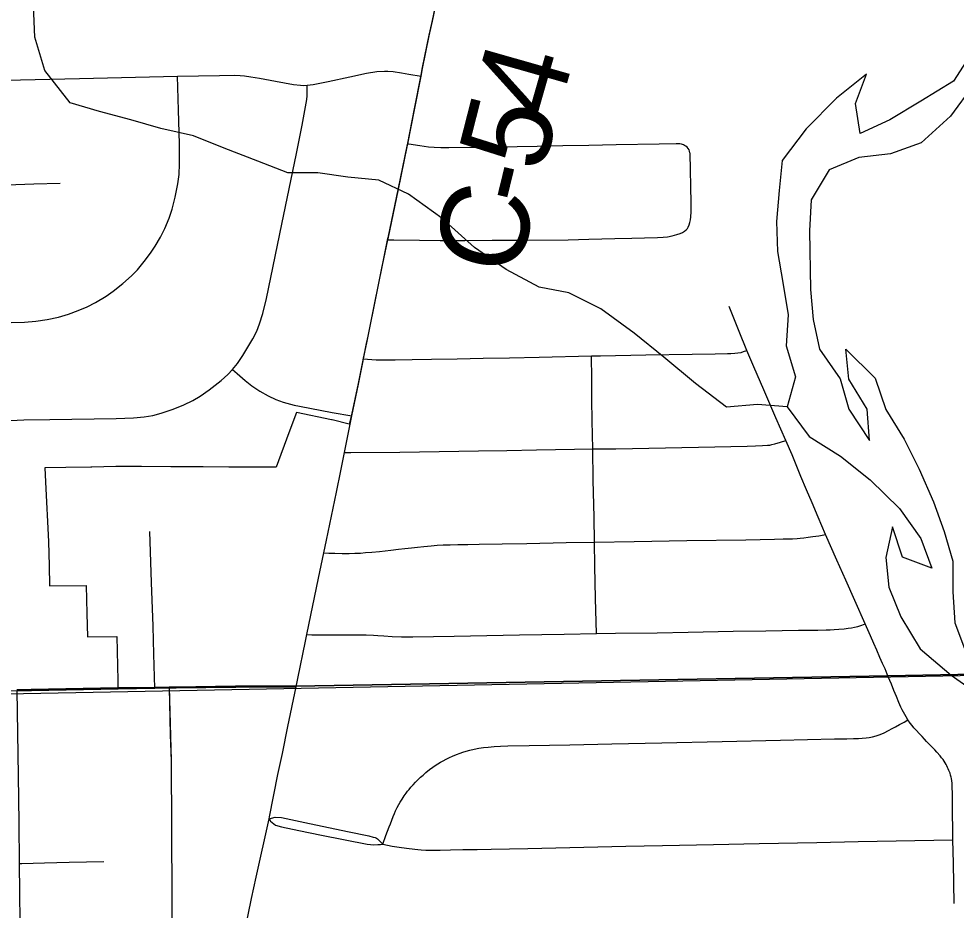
# Model space of a CAD drawing. Extents: x -6.4 to 34, y -4.2 to 22.
# Drawn here: x 4.056 to 4.662, y 15.706 to 16.282 of the extents above; entities that cross this region are included whole.
import ezdxf

# ---------------------------------------------------------------- set-up
doc = ezdxf.new("R2010")
doc.units = 0
for name, color, linetype in [('GM_X_City_Street', 7, 'Continuous'), ('GM_X_Corporation', 7, 'Continuous'), ('GM_X_County_Road', 7, 'Continuous'), ('GM_X_County_Road_Text', 7, 'Continuous'), ('GM_X_Major_River', 7, 'Continuous'), ('GM_X_Minor_River', 7, 'Continuous'), ('GM_X_Township_Road', 7, 'Continuous')]:
    doc.layers.add(name, color=color, linetype=linetype)

msp = doc.modelspace()

# ---------------------------------------------------------------- linework, layer by layer
at = {"layer": 'GM_X_City_Street'}
for points in [[(4.29434, 16.13894), (4.2983, 16.1389), (4.31489, 16.13876), (4.32819, 16.13864), (4.34402, 16.1386), (4.36176, 16.13867), (4.3816, 16.13883), (4.41095, 16.13907), (4.42419, 16.13937), (4.44106, 16.13976), (4.45211, 16.14005), (4.46018, 16.14027), (4.4686, 16.14049), (4.47232, 16.14072), (4.47512, 16.141), (4.47823, 16.14158), (4.48114, 16.14241), (4.48324, 16.1431), (4.48483, 16.14382), (4.48624, 16.1446), (4.48725, 16.14536), (4.48805, 16.1462), (4.48852, 16.14707), (4.48914, 16.14861), (4.48962, 16.1501), (4.49006, 16.15195), (4.49029, 16.15384), (4.4904, 16.15702), (4.49038, 16.1629), (4.48979, 16.19469), (4.48968, 16.19532), (4.48947, 16.19628), (4.48909, 16.19718), (4.48854, 16.19804), (4.48786, 16.19888), (4.48701, 16.19957), (4.48621, 16.20006), (4.48555, 16.20043), (4.48428, 16.2008), (4.48314, 16.20097), (4.48214, 16.201), (4.48069, 16.201), (4.46975, 16.20085), (4.44199, 16.20047), (4.42426, 16.20006), (4.4075, 16.19967), (4.39089, 16.19927), (4.35195, 16.19863), (4.3337, 16.19836), (4.3285, 16.19843), (4.32419, 16.19861), (4.32067, 16.19884), (4.31507, 16.19971), (4.308, 16.20087), (4.30722, 16.20099)], [(4.66044, 15.70999), (4.65997, 15.73598), (4.65956, 15.75111), (4.65941, 15.77505), (4.65942, 15.78015), (4.65926, 15.78598), (4.65918, 15.78763), (4.65902, 15.78911), (4.65877, 15.7906), (4.65852, 15.79166), (4.6582, 15.79289), (4.65779, 15.79405), (4.65746, 15.79495), (4.65705, 15.79594), (4.65664, 15.79693), (4.65623, 15.79783), (4.65573, 15.79882), (4.65524, 15.79972), (4.65467, 15.80079), (4.65401, 15.80186), (4.65327, 15.80294), (4.65236, 15.80417), (4.65146, 15.80532), (4.64937, 15.8077), (4.648, 15.80919), (4.64612, 15.81116), (4.64407, 15.81322), (4.64265, 15.81468), (4.64131, 15.81606), (4.63971, 15.81775), (4.63798, 15.81964), (4.63581, 15.82195), (4.63445, 15.82342), (4.63322, 15.82491), (4.63194, 15.82656), (4.63058, 15.82859), (4.62939, 15.83051), (4.62853, 15.83198), (4.62763, 15.83363), (4.6268, 15.83519), (4.62603, 15.83684), (4.62541, 15.83824), (4.62472, 15.83981), (4.62319, 15.84367), (4.62156, 15.84768), (4.61996, 15.85161), (4.61791, 15.85654), (4.61581, 15.86152), (4.61413, 15.86511), (4.61244, 15.869), (4.61047, 15.87361), (4.60858, 15.87797), (4.60644, 15.88291), (4.60291, 15.89064), (4.59634, 15.90586), (4.59048, 15.91892), (4.58468, 15.93186), (4.57729, 15.94847), (4.57253, 15.95974), (4.56866, 15.9689), (4.56508, 15.97739), (4.56144, 15.98599), (4.55578, 15.99989), (4.55175, 16.00919), (4.54527, 16.02383), (4.53738, 16.04193), (4.53098, 16.0569), (4.52646, 16.06743), (4.52146, 16.07977), (4.51508, 16.09592)], [(4.27864, 16.06202), (4.28115, 16.06179), (4.28395, 16.06154), (4.28683, 16.06138), (4.28995, 16.06129), (4.2939, 16.06133), (4.29907, 16.06137), (4.31001, 16.06156), (4.32266, 16.06179), (4.33921, 16.06212), (4.35591, 16.06239), (4.37294, 16.06271), (4.39224, 16.06317), (4.42596, 16.06387), (4.43182, 16.06399), (4.4611, 16.06454), (4.49104, 16.06502), (4.50592, 16.06525), (4.51399, 16.06541), (4.51613, 16.0655), (4.51875, 16.06566), (4.52056, 16.06582), (4.52279, 16.06623), (4.52433, 16.06669), (4.52646, 16.06743)], [(4.42921, 15.88438), (4.4286, 15.90718), (4.4282, 15.92799), (4.42788, 15.94344), (4.42765, 15.95974), (4.42717, 15.98351), (4.42681, 16.00377), (4.42637, 16.02192), (4.42626, 16.03573), (4.42615, 16.04897), (4.42596, 16.06387)], [(4.2664, 16.0015), (4.27044, 16.00151), (4.3022, 16.00159), (4.35293, 16.00252), (4.37135, 16.00284), (4.39052, 16.00323), (4.41494, 16.00363), (4.42681, 16.00377), (4.44175, 16.00394), (4.49522, 16.00497), (4.52663, 16.00549), (4.53214, 16.00569), (4.5365, 16.00593), (4.53971, 16.00618), (4.54123, 16.00632), (4.5425, 16.00659), (4.54456, 16.00708), (4.54818, 16.00814), (4.55175, 16.00919)], [(4.1437, 15.84907), (4.1431, 15.87118), (4.14254, 15.88911), (4.14149, 15.91732), (4.14053, 15.95047)], [(4.25298, 15.93658), (4.25618, 15.93649), (4.26004, 15.93637), (4.26481, 15.93624), (4.26942, 15.93623), (4.27311, 15.93631), (4.27657, 15.93649), (4.27986, 15.93672), (4.28397, 15.93705), (4.28891, 15.93754), (4.29269, 15.93794), (4.29631, 15.93835), (4.30124, 15.93892), (4.30536, 15.93941), (4.30955, 15.9399), (4.31358, 15.94031), (4.3177, 15.94072), (4.32246, 15.94113), (4.32617, 15.94146), (4.3302, 15.9417), (4.33455, 15.94186), (4.33957, 15.94202), (4.34607, 15.9421), (4.35339, 15.94226), (4.3682, 15.94245), (4.38431, 15.94265), (4.40973, 15.94321), (4.42788, 15.94344), (4.45356, 15.94392), (4.48761, 15.94455), (4.52578, 15.94502), (4.54428, 15.94542), (4.54995, 15.94556), (4.55382, 15.94566), (4.55604, 15.94576), (4.55901, 15.94589), (4.56088, 15.94607), (4.56327, 15.94631), (4.56599, 15.94664), (4.56911, 15.94711), (4.5729, 15.9477), (4.57729, 15.94847)], [(4.24204, 15.8837), (4.24514, 15.88368), (4.25657, 15.88359), (4.27442, 15.88358), (4.28042, 15.88349), (4.28511, 15.88332), (4.28798, 15.88317), (4.29177, 15.88291), (4.29712, 15.88257), (4.3032, 15.8824), (4.3106, 15.8824), (4.33717, 15.88279), (4.37936, 15.88358), (4.40831, 15.88397), (4.42921, 15.88438), (4.44154, 15.88461), (4.46843, 15.88496), (4.48842, 15.88524), (4.51753, 15.88588), (4.53875, 15.88616), (4.55989, 15.8865), (4.5723, 15.88666), (4.57765, 15.88681), (4.5802, 15.8869), (4.58299, 15.8871), (4.58587, 15.88731), (4.58925, 15.88755), (4.59204, 15.8878), (4.5941, 15.88804), (4.59608, 15.88845), (4.59813, 15.88903), (4.60069, 15.88982), (4.60291, 15.89064)], [(4.2911, 15.74817), (4.29313, 15.75376), (4.2942, 15.75672), (4.29519, 15.75935), (4.29602, 15.7614), (4.29692, 15.76371), (4.29783, 15.76609), (4.29857, 15.76798), (4.29939, 15.76987), (4.3003, 15.77185), (4.30137, 15.77382), (4.30227, 15.7753), (4.30355, 15.77725), (4.30491, 15.77941), (4.30615, 15.78114), (4.30715, 15.78246), (4.30812, 15.78369), (4.30927, 15.785), (4.31069, 15.78657), (4.31224, 15.78828), (4.31396, 15.79001), (4.31553, 15.79149), (4.31709, 15.79289), (4.319, 15.79454), (4.32129, 15.79642), (4.32335, 15.79798), (4.32491, 15.79905), (4.32656, 15.80012), (4.32845, 15.80127), (4.33009, 15.80217), (4.33207, 15.80324), (4.33413, 15.80423), (4.3361, 15.80513), (4.33865, 15.8062), (4.34104, 15.8071), (4.34292, 15.80776), (4.34498, 15.80842), (4.34745, 15.80907), (4.35016, 15.80973), (4.35321, 15.8103), (4.35625, 15.81071), (4.3593, 15.81104), (4.36308, 15.81136), (4.36711, 15.8116), (4.37188, 15.81177), (4.38561, 15.81201), (4.4121, 15.81248), (4.43916, 15.81304), (4.47148, 15.81367), (4.51038, 15.81464), (4.54821, 15.81559), (4.58316, 15.81631), (4.59114, 15.81639), (4.59542, 15.81647), (4.59854, 15.81655), (4.60093, 15.81671), (4.6035, 15.81697), (4.60545, 15.81725), (4.60759, 15.81769), (4.61006, 15.81835), (4.61253, 15.81917), (4.61516, 15.82032), (4.61796, 15.82163), (4.62043, 15.82295), (4.62257, 15.8241), (4.6252, 15.82558), (4.62816, 15.82722), (4.63058, 15.82859)], [(4.21758, 15.76472), (4.2214, 15.76569), (4.22554, 15.76549), (4.24063, 15.76224), (4.26832, 15.75641), (4.28213, 15.75353), (4.28476, 15.75287), (4.28616, 15.75246), (4.28698, 15.75205), (4.28756, 15.75163), (4.28854, 15.75073), (4.28961, 15.74966), (4.2911, 15.74817)], [(4.21758, 15.76472), (4.21856, 15.76313), (4.22176, 15.76057), (4.22569, 15.75935), (4.23674, 15.75709), (4.25155, 15.75412), (4.28099, 15.74826), (4.28312, 15.74793), (4.28526, 15.74785), (4.28781, 15.74801), (4.28954, 15.74809), (4.2911, 15.74817)], [(4.2911, 15.74817), (4.29718, 15.74701), (4.30318, 15.74601), (4.3082, 15.74535), (4.31363, 15.74478), (4.31584, 15.74464), (4.31897, 15.74444), (4.32275, 15.74436), (4.3281, 15.74439), (4.33485, 15.74451), (4.34274, 15.74469), (4.35203, 15.74488), (4.36124, 15.74507), (4.38493, 15.74555), (4.44826, 15.7469), (4.47195, 15.74746), (4.50484, 15.7481), (4.53437, 15.74865), (4.57171, 15.74937), (4.59836, 15.74993), (4.65956, 15.75111)]]:
    msp.add_lwpolyline(points, dxfattribs=at)
at = {"layer": 'GM_X_Corporation'}
for points in [[(4.32878, 16.30877), (4.32292, 16.28089), (4.32092, 16.27139), (4.31657, 16.25039), (4.3156, 16.24542), (4.31133, 16.2236), (4.30702, 16.20155), (4.30664, 16.19956), (4.30094, 16.17237), (4.29431, 16.14028), (4.29422, 16.13988), (4.28045, 16.07241), (4.27844, 16.06257), (4.27795, 16.06015), (4.27515, 16.04617), (4.2709, 16.02585), (4.26942, 16.01979), (4.25827, 16.02251), (4.25817, 16.02254), (4.25808, 16.02257), (4.25798, 16.02259), (4.25789, 16.02261), (4.23524, 16.02735), (4.23036, 16.01424), (4.22206, 15.99193), (4.20424, 15.99202), (4.19724, 15.99206), (4.19162, 15.99209), (4.17488, 15.99218), (4.15558, 15.99228), (4.15407, 15.99229), (4.13512, 15.99239), (4.1186, 15.99247), (4.10294, 15.99208), (4.10223, 15.99206), (4.08613, 15.99173), (4.07253, 15.99157), (4.07323, 15.97799), (4.07474, 15.94832), (4.07487, 15.94366), (4.07529, 15.9285), (4.07565, 15.91517), (4.09924, 15.91546), (4.09973, 15.89748), (4.10015, 15.88232), (4.11909, 15.88253), (4.11987, 15.85408), (4.1197, 15.84929), (4.1435, 15.84962), (4.15304, 15.84978), (4.1542, 15.80243), (4.15484, 15.66937)], [(5.03555, 15.86533), (4.94435, 15.86353), (4.89919, 15.86252), (4.61771, 15.8571), (4.23487, 15.85045), (4.22882, 15.85045), (4.19578, 15.85041), (4.15725, 15.84984), (4.15304, 15.84978), (4.1435, 15.84962), (4.1197, 15.84929), (4.06372, 15.84822), (4.05453, 15.84804)], [(4.05453, 15.84804), (4.06372, 15.84822), (4.1197, 15.84929), (4.1435, 15.84962), (4.15304, 15.84978), (4.15725, 15.84984), (4.19578, 15.85041), (4.22882, 15.85045), (4.23487, 15.85045), (4.61771, 15.8571), (4.89919, 15.86252), (4.94435, 15.86353), (5.03555, 15.86533)]]:
    msp.add_lwpolyline(points, dxfattribs=at)
msp.add_lwpolyline([(3.94651, 15.8436), (4.81021, 15.86007), (4.82849, 15.2133), (4.41851, 15.20239), (4.0324, 15.19212), (3.70187, 15.18694), (3.30855, 15.18118), (3.23887, 15.18016), (3.22314, 15.8313)], close=True, dxfattribs=at)
at = {"layer": 'GM_X_County_Road'}
for p, q in [((4.1437, 15.84907), (4.15324, 15.84922)), ((4.1199, 15.84874), (4.1437, 15.84907))]:
    msp.add_line(p, q, dxfattribs=at)
for points in [[(4.27109, 16.02529), (4.27534, 16.04561), (4.27815, 16.05959), (4.27864, 16.06202), (4.28065, 16.07185), (4.28165, 16.07677), (4.28579, 16.09714), (4.29095, 16.12254), (4.29434, 16.13894), (4.29451, 16.13972), (4.30114, 16.17182), (4.30684, 16.19901), (4.30722, 16.20099), (4.31153, 16.22305), (4.3158, 16.24487), (4.31677, 16.24984), (4.32112, 16.27084), (4.32312, 16.28033), (4.32897, 16.30822), (4.33191, 16.32276), (4.33391, 16.33314), (4.34092, 16.36958), (4.3432, 16.38194)], [(4.23507, 15.8499), (4.23619, 15.85529), (4.24118, 15.87956), (4.24204, 15.8837), (4.24962, 15.92029), (4.25298, 15.93658), (4.25466, 15.94473), (4.26106, 15.97577), (4.26395, 15.98957), (4.2664, 16.0015), (4.26705, 16.00464), (4.27109, 16.02529)], [(4.15324, 15.84922), (4.15745, 15.84928), (4.19598, 15.84986), (4.22901, 15.84989), (4.23507, 15.8499)], [(4.19951, 15.68041), (4.20622, 15.71312), (4.20924, 15.72684), (4.21758, 15.76472), (4.21784, 15.76592), (4.22333, 15.79328), (4.22617, 15.80685), (4.22977, 15.82429), (4.23507, 15.8499)], [(3.51043, 15.83841), (3.55892, 15.83944), (3.60948, 15.8405), (3.64235, 15.8411), (3.67734, 15.84142), (3.68745, 15.84152), (3.70213, 15.84176), (3.77183, 15.8429), (3.79297, 15.84325), (3.85029, 15.84411), (3.9112, 15.84501), (3.92879, 15.84528), (3.97764, 15.84601), (4.05473, 15.84749), (4.06392, 15.84766), (4.1199, 15.84874)]]:
    msp.add_lwpolyline(points, dxfattribs=at)
at = {"layer": 'GM_X_Major_River'}
for points in [[(4.67245, 16.2609), (4.65997, 16.24165), (4.63902, 16.22868), (4.61882, 16.21648), (4.59968, 16.20772), (4.59663, 16.22702), (4.60381, 16.24615), (4.58443, 16.23055), (4.56476, 16.21077), (4.54928, 16.19032), (4.54741, 16.17092), (4.54556, 16.15077), (4.54634, 16.13142), (4.54979, 16.11138), (4.55325, 16.09058), (4.55178, 16.07042), (4.55788, 16.05044), (4.55261, 16.03096), (4.56664, 16.0119), (4.58699, 15.99905), (4.60625, 15.9839), (4.6252, 15.96533), (4.63886, 15.94588), (4.64608, 15.92667), (4.62699, 15.93386), (4.62052, 15.95346), (4.61639, 15.93363), (4.61831, 15.91431), (4.62591, 15.89512), (4.63846, 15.87451), (4.65852, 15.85748), (4.67966, 15.84274)], [(4.6729, 16.23927), (4.65817, 16.21884), (4.63921, 16.20173), (4.61928, 16.19448), (4.59887, 16.19214), (4.57972, 16.18414), (4.568, 16.16491), (4.5669, 16.14477), (4.56769, 16.10683), (4.56923, 16.0875), (4.57342, 16.06823), (4.5867, 16.04915), (4.59241, 16.02954), (4.60572, 16.00932), (4.60416, 16.02941), (4.59239, 16.0489), (4.59047, 16.06821), (4.60942, 16.04964), (4.61629, 16.02929), (4.62805, 16.01018), (4.63793, 15.99065), (4.64708, 15.96959), (4.65392, 15.95037), (4.65963, 15.93114), (4.65966, 15.9114), (4.66084, 15.89131), (4.66846, 15.87135)]]:
    msp.add_lwpolyline(points, dxfattribs=at)
at = {"layer": 'GM_X_Minor_River'}
msp.add_lwpolyline([(4.55261, 16.03096), (4.53325, 16.03245), (4.51321, 16.03088), (4.49319, 16.04602), (4.47276, 16.06304), (4.45349, 16.07858), (4.43195, 16.09444), (4.41128, 16.10463), (4.39225, 16.1084), (4.37081, 16.11971), (4.35043, 16.13408), (4.3292, 16.15298), (4.30766, 16.16846), (4.28853, 16.17755), (4.26841, 16.17939), (4.24903, 16.1824), (4.22971, 16.18237), (4.21023, 16.18992), (4.18846, 16.19819), (4.1686, 16.20611), (4.14766, 16.21098), (4.12822, 16.21664), (4.10803, 16.2219), (4.08897, 16.22757), (4.07263, 16.24848), (4.06612, 16.26998), (4.06531, 16.29046)], dxfattribs=at)
at = {"layer": 'GM_X_Township_Road'}
for points in [[(4.03743, 16.24208), (4.09493, 16.24339), (4.1584, 16.24469), (4.18562, 16.24531), (4.19552, 16.24541), (4.19894, 16.24521), (4.20164, 16.245), (4.20586, 16.24445), (4.21141, 16.24357), (4.22175, 16.24157), (4.2334, 16.23931), (4.23783, 16.23888), (4.23986, 16.23878), (4.24215, 16.23897), (4.24605, 16.2394), (4.25582, 16.24128), (4.26975, 16.24442), (4.28064, 16.24674), (4.28733, 16.24774), (4.29218, 16.24809), (4.29432, 16.24809), (4.29769, 16.24782), (4.30315, 16.247), (4.308, 16.24618), (4.3158, 16.24487)], [(4.05075, 16.08562), (4.05941, 16.08575), (4.06678, 16.08641), (4.07411, 16.0875), (4.08135, 16.08903), (4.08786, 16.09093), (4.09424, 16.0932), (4.09987, 16.09566), (4.10534, 16.09849), (4.11225, 16.10257), (4.11678, 16.10575), (4.12305, 16.11077), (4.12857, 16.1157), (4.13242, 16.11968), (4.13678, 16.12486), (4.14085, 16.1303), (4.14393, 16.13491), (4.14735, 16.14074), (4.15012, 16.14626), (4.15301, 16.15307), (4.15502, 16.15888), (4.15695, 16.16666), (4.1586, 16.17515), (4.15935, 16.18126), (4.15969, 16.18803), (4.15968, 16.20105), (4.15896, 16.22281), (4.1584, 16.24469)], [(4.0504, 16.02219), (4.05903, 16.02266), (4.07577, 16.02289), (4.11868, 16.02344), (4.12992, 16.02383), (4.13679, 16.0245), (4.14238, 16.02546), (4.14786, 16.02691), (4.15557, 16.02953), (4.16255, 16.03235), (4.16821, 16.03509), (4.1731, 16.03796), (4.17873, 16.04195), (4.18664, 16.04806), (4.19089, 16.05181), (4.19398, 16.05504), (4.19714, 16.05895), (4.20059, 16.06421), (4.20698, 16.07493), (4.20955, 16.07999), (4.21142, 16.08468), (4.21348, 16.09128), (4.21589, 16.10098), (4.2259, 16.14908), (4.23523, 16.19479), (4.23899, 16.21307), (4.24203, 16.22961), (4.24223, 16.23213), (4.24225, 16.23529), (4.24215, 16.23897)], [(4.03899, 16.17428), (4.04808, 16.17455), (4.06538, 16.17508), (4.0826, 16.17568)], [(4.19398, 16.05504), (4.19687, 16.05255), (4.20213, 16.04802), (4.20649, 16.04459), (4.21164, 16.04118), (4.21702, 16.03817), (4.22204, 16.03582), (4.22665, 16.0341), (4.2338, 16.03215), (4.23719, 16.03136), (4.2583, 16.02726), (4.27109, 16.02529)], [(4.1544, 15.80187), (4.15392, 15.81911), (4.15324, 15.84922)], [(4.05627, 15.61402), (4.05685, 15.67935), (4.05626, 15.7357), (4.05599, 15.76205), (4.05553, 15.79265), (4.05473, 15.84749)], [(4.05626, 15.7357), (4.05783, 15.73573), (4.0724, 15.73608), (4.08838, 15.7365), (4.09947, 15.73679), (4.11068, 15.73708)]]:
    msp.add_lwpolyline(points, dxfattribs=at)

# ---------------------------------------------------------------- texts
at = {"layer": 'GM_X_County_Road_Text'}
for s, rotation, p in [('4', 74.10178, (4.403, 16.21482)), ('5', 75.6703, (4.39444, 16.1813)), ('-', 76.28748, (4.38895, 16.15879)), ('C', 76.5161, (4.37808, 16.11347))]:
    msp.add_text(s, height=0.05682, rotation=rotation, dxfattribs=at).set_placement(p)

doc.saveas('drawing.dxf')
